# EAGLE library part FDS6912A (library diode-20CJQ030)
Fairchild's FDS6912A Dual N-Channel Logic Level PowerTrench MOSFET General Description: These N-Channel Logic Level MOSFETs are produced using Fairchild Semiconductor's advanced PowerTrench process that has been especially tailored to minimize the on-state resistance and yet maintain superior switching performance. These devices are well suited for low voltage and battery powered applications where low in-line power loss and fast switching are required. Features: 6 A, 30 V. RDS(ON) = 28 mOhm @ VGS = 10 V RDS(ON) = 35 mOhm @ VGS = 4.5 V Fast switching speed Low gate charge High performance trench technology for extremely low RDS(ON) High power and current handling capability Please send any comments to: messi@users.sourceforge.net
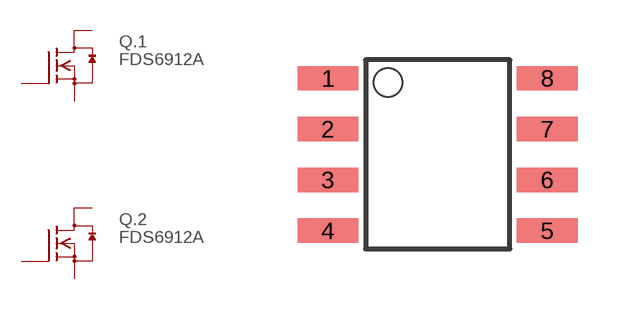
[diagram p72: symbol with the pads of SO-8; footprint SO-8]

Designator prefix Q; gates .1=IGFET-4-N-CH .2=IGFET-4-N-CH

## FDS6912A  [SO-8]
1  .2:S  pas
2  .2:G  pas
3  .1:S  pas
4  .1:G  pas
5  .1:D  pas
6  .1:D  pas
7  .2:D  pas
8  .2:D  pas

## Footprint SO-8 (pad centres in mm)
small outline
smd 1.524 x 0.61: 1 -2.743,1.27; 2 -2.743,0; 3 -2.743,-1.27; 4 -2.743,-2.54; 5 2.743,-2.54; 6 2.743,-1.27; 7 2.743,0; 8 2.743,1.27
